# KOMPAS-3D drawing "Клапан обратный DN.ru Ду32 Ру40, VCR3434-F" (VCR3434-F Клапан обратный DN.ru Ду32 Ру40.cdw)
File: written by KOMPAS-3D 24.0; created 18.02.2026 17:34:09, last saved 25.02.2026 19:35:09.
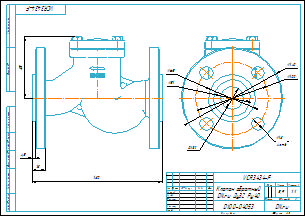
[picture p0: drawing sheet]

Document properties: art: D100-04053; Автор: R2D2; Форматы листов документа: A3; Полное имя файла: VCR3434-F Клапан обратный DN.ru Ду32 Ру40.m3d; Масса: 5.9; Наименование: Клапан обратный DN.ru Ду32 Ру40; Количество листов документа: 1; Примечание: D100-04053

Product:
- Part/product: Клапан обратный DN.ru Ду32 Ру40  | designation VCR3434-F
    Масса: 5.9
    Раздел спецификации: Прочие изделия
    Примечание: D100-04053
    additional columns: D100-04053

Views: Вид 1, Спереди, Проекционный вид 2
Referenced files in E:\Работа\Зайцев\VCR3434-F Клапан обратный DN.ru Ду15-300\DN32\: VCR3434-F Клапан обратный DN.ru Ду32 Ру40.m3d
Referenced files in E:\Работа\Зайцев\Для компаса\: чертеж DN.ru А3.cdt
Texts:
  VCR3434-F
  чертеж DN.ru А3.cdt
  Клапан обратный
  DN.ru Ду32 Ру40
  prop
  Клапан обратный DN.ru Ду32 Ру40
  VCR3434-F Клапан обратный DN.ru Ду32 Ру40
Dimensions and other numbers on the sheet: 0; 3; 2; 4; 140; 100; 18; 4 отв.; 32; 51; 65; 4,5; 180; 85; 1:1; 1; 5,9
